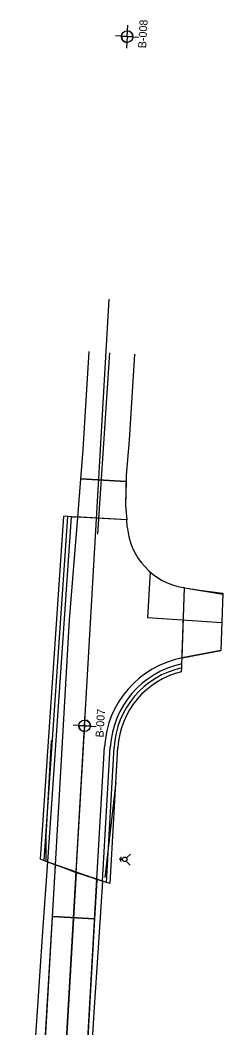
# Model space of a CAD drawing. Extents: x 1973866 to 1974130, y 734965 to 738427.
# Drawn here: x 1974024 to 1974130, y 737903 to 738427 of the extents above; entities that cross this region are included whole.
import ezdxf

# ---------------------------------------------------------------- set-up
doc = ezdxf.new("R2010")
doc.units = 0
for name, color, linetype in [('CM_Corridor_Range_Conceptual', 7, 'Continuous'), ('DR_P_Cells', 7, 'Continuous'), ('DR_P_Storm_Sewer', 7, 'Continuous'), ('DR_X_Cells', 7, 'Continuous'), ('DR_X_GenericNode', 7, 'Continuous'), ('DR_X_Storm_Sewer', 7, 'Continuous'), ('MD_P_ACIC_B', 7, 'Continuous'), ('MD_P_Surface_Asphalt_Concrete_Base', 7, 'Continuous'), ('PF_X_Ground_Line', 7, 'Continuous'), ('PV_P_Saw_Cut_Line', 7, 'Continuous'), ('PV_P_Shoulder', 7, 'Continuous'), ('SC_ProfileRun2', 7, 'Continuous'), ('SC_ProfileRun3', 7, 'Continuous'), ('SC_Scratch1', 7, 'Continuous'), ('SH_Text', 7, 'Continuous')]:
    doc.layers.add(name, color=color, linetype=linetype)

msp = doc.modelspace()

# ---------------------------------------------------------------- linework, layer by layer
at = {"layer": 'CM_Corridor_Range_Conceptual'}
for p, q in [((1974034.86, 737990.69), (1974047.1, 738169.16)), ((1974049.09, 738169.02), (1974047.1, 738169.16)), ((1974108.27, 738088.16), (1974108.34, 738090.22)), ((1974071.15, 737977.95), (1974075.17, 738048.77)), ((1974034.86, 737990.69), (1974036.81, 737989.96)), ((1974071.15, 737977.95), (1974069.19, 737978.6))]:
    msp.add_line(p, q, dxfattribs=at)
msp.add_arc((1974118.11, 738046.3), 43, 103.2394, 176.7032, dxfattribs=at)
at = {"layer": 'DR_P_Cells'}
msp.add_line((1974024.31, 737478.61), (1974070.59, 738282.05), dxfattribs=at)
at = {"layer": 'DR_P_Storm_Sewer'}
for p, q in [((1974038.77, 737989.23), (1974051.09, 738168.89)), ((1974051.09, 738168.89), (1974053.09, 738168.77)), ((1974108.41, 738092.29), (1974108.52, 738095.37)), ((1974067.22, 737979.25), (1974071.18, 738049)), ((1974038.77, 737989.23), (1974042.65, 737987.79)), ((1974067.22, 737979.25), (1974064.23, 737980.24))]:
    msp.add_line(p, q, dxfattribs=at)
msp.add_arc((1974118.11, 738046.3), 47, 101.9137, 176.7032, dxfattribs=at)
at = {"layer": 'DR_X_Cells'}
for p, q in [((1974036.81, 737989.96), (1974049.09, 738169.02)), ((1974051.09, 738168.89), (1974049.09, 738169.02)), ((1974108.34, 738090.22), (1974108.41, 738092.29)), ((1974069.19, 737978.6), (1974073.18, 738048.89)), ((1974036.81, 737989.96), (1974038.77, 737989.23)), ((1974069.19, 737978.6), (1974067.22, 737979.25))]:
    msp.add_line(p, q, dxfattribs=at)
msp.add_arc((1974118.11, 738046.3), 45, 102.5461, 176.7032, dxfattribs=at)
at = {"layer": 'DR_X_GenericNode'}
for p, q in [((1974109.8, 738131.88), (1974129.7, 738128.65)), ((1974108.52, 738095.37), (1974128.67, 738099.31)), ((1974036.52, 737881.37), (1974042.65, 737987.79)), ((1974058.06, 737873.15), (1974064.23, 737980.24))]:
    msp.add_line(p, q, dxfattribs=at)
for points in [[(1974054.28, 738168.7), (1974057.05, 738203.85), (1974060.26, 738254.83)], [(1974083.73, 738253.45), (1974080.96, 738208.69), (1974079.5, 738190.53), (1974079.07, 738174.87), (1974079.73, 738167.21)]]:
    msp.add_lwpolyline(points, dxfattribs=at)
at = {"layer": 'DR_X_Storm_Sewer'}
for p, q in [((1974064.78, 738159.83), (1974070.99, 738254.17)), ((1974090.51, 738116.5), (1974129.18, 738113.79)), ((1974053.41, 737983.81), (1974057.86, 738060.93)), ((1974053.41, 737983.81), (1974024.31, 737478.61))]:
    msp.add_line(p, q, dxfattribs=at)
at = {"layer": 'MD_P_ACIC_B'}
for centre in [(1974079.95, 738418.7), (1974057.81, 738060.06)]:
    msp.add_circle(centre, 0.05, dxfattribs=at)
at = {"layer": 'MD_P_Surface_Asphalt_Concrete_Base'}
for p, q in [((1974079.95, 738418.7), (1974080.29, 738424.7)), ((1974079.95, 738418.7), (1974080.12, 738421.7)), ((1974079.95, 738418.7), (1974073.96, 738419.04)), ((1974076.96, 738418.87), (1974079.95, 738418.7)), ((1974079.95, 738418.7), (1974079.62, 738412.71)), ((1974079.95, 738418.7), (1974079.78, 738415.71)), ((1974079.95, 738418.7), (1974085.94, 738418.37)), ((1974082.95, 738418.54), (1974079.95, 738418.7)), ((1974057.81, 738060.06), (1974058.14, 738066.05)), ((1974057.81, 738060.06), (1974057.97, 738063.06)), ((1974057.81, 738060.06), (1974051.82, 738060.4)), ((1974054.81, 738060.23), (1974057.81, 738060.06)), ((1974057.81, 738060.06), (1974057.47, 738054.07)), ((1974057.81, 738060.06), (1974057.64, 738057.07)), ((1974057.81, 738060.06), (1974063.8, 738059.73)), ((1974060.8, 738059.89), (1974057.81, 738060.06))]:
    msp.add_line(p, q, dxfattribs=at)
for centre in [(1974079.95, 738418.7), (1974057.81, 738060.06)]:
    msp.add_circle(centre, 3, dxfattribs=at)
for centre, start, end in [((1974079.95, 738418.7), 356.7892, 86.7892), ((1974079.95, 738418.7), 176.7892, 266.7892), ((1974057.81, 738060.06), 356.7892, 86.7892), ((1974057.81, 738060.06), 176.7892, 266.7892)]:
    msp.add_arc(centre, 3, start, end, dxfattribs=at)
at = {"layer": 'PF_X_Ground_Line'}
for p, q in [((1974036.22, 737955.55), (1974038.77, 737989.23)), ((1974038.77, 737989.23), (1974067.22, 737979.25)), ((1974043.12, 737987.61), (1974044.38, 737987.14)), ((1974044.38, 737987.14), (1974047.13, 737986.12)), ((1974047.13, 737986.12), (1974048.5, 737985.6)), ((1974048.5, 737985.6), (1974049.8, 737985.12)), ((1974049.8, 737985.12), (1974051.25, 737984.58)), ((1974067.22, 737979.25), (1974065.47, 737952.45)), ((1974031.43, 737883.28), (1974036.22, 737955.55)), ((1974065.47, 737952.45), (1974062.67, 737910.86)), ((1974062.67, 737910.86), (1974060.68, 737879.88))]:
    msp.add_line(p, q, dxfattribs=at)
for points in [[(1974064.2, 737979.74), (1974063.04, 737959.6), (1974041.1, 737960.86), (1974042.62, 737987.29)], [(1974051.25, 737984.58), (1974052.45, 737984.13), (1974063.75, 737980.4)], [(1974036.52, 737881.37), (1974041.1, 737960.81), (1974063.03, 737959.55), (1974058.06, 737873.15)]]:
    msp.add_lwpolyline(points, dxfattribs=at)
for centre, start, end in [((1974042.65, 737987.79), 266.7002, 339.5569), ((1974064.23, 737980.24), 161.7002, 266.7032)]:
    msp.add_arc(centre, 0.5, start, end, dxfattribs=at)
at = {"layer": 'PV_P_Saw_Cut_Line'}
for p, q in [((1974037.78, 738002.49), (1974040.58, 738052.41)), ((1974074.15, 738030.8), (1974068.3, 737981.15)), ((1974037.83, 737989.97), (1974037.78, 738002.49))]:
    msp.add_line(p, q, dxfattribs=at)
at = {"layer": 'PV_P_Shoulder'}
for p, q in [((1974077.5, 737990.64), (1974075.78, 737990.74)), ((1974076.71, 737991.89), (1974076.57, 737989.49)), ((1974079.5, 737989.68), (1974081.46, 737987.49)), ((1974079.59, 737991.37), (1974081.78, 737993.33))]:
    msp.add_line(p, q, dxfattribs=at)
msp.add_circle((1974078.69, 737990.58), 1.2, dxfattribs=at)
at = {"layer": 'SC_ProfileRun2'}
msp.add_line((1974091.87, 738140.16), (1974090.51, 738116.5), dxfattribs=at)
at = {"layer": 'SC_ProfileRun3'}
msp.add_line((1974055.08, 738168.65), (1974053.09, 738168.77), dxfattribs=at)
at = {"layer": 'SC_Scratch1'}
for p, q in [((1974079.73, 738167.21), (1974053.09, 738168.77)), ((1974080.04, 738163.52), (1974079.73, 738167.21)), ((1974108.59, 738097.42), (1974109.8, 738131.88)), ((1974109.8, 738131.88), (1974109.3, 738131.96)), ((1974108.52, 738095.37), (1974108.59, 738097.42)), ((1974064.23, 737980.24), (1974068.2, 738049.17)), ((1974052.45, 737984.13), (1974042.65, 737987.79)), ((1974064.23, 737980.24), (1974052.45, 737984.13))]:
    msp.add_line(p, q, dxfattribs=at)
msp.add_lwpolyline([(1974042.65, 737987.79), (1974050, 738115.18), (1974054.28, 738168.7)], dxfattribs=at)
for centre, radius, start, end in [((1974114.91, 738166.51), 35, 184.9021, 260.7716), ((1974118.11, 738046.3), 50, 101.0627, 176.7032)]:
    msp.add_arc(centre, radius, start, end, dxfattribs=at)
at = {"layer": 'SH_Text'}
msp.add_line((1974079.41, 738187.26), (1974055.85, 738188.64), dxfattribs=at)
for points in [[(1974079.07, 738174.87), (1974079.73, 738167.21), (1974054.28, 738168.7), (1974055.85, 738188.64), (1974079.41, 738187.26)], [(1974117.59, 738130.62), (1974129.72, 738129.07), (1974128.67, 738099.31), (1974108.52, 738095.37), (1974109.8, 738131.88)]]:
    msp.add_lwpolyline(points, close=True, dxfattribs=at)

# ---------------------------------------------------------------- texts
at = {"layer": 'SC_Scratch1'}
for s, p in [('B-008', (1974089.79, 738412.55)), ('B-007', (1974067.64, 738053.91))]:
    msp.add_text(s, height=4.167, rotation=86.7892, dxfattribs=at).set_placement(p)

doc.saveas('drawing.dxf')
